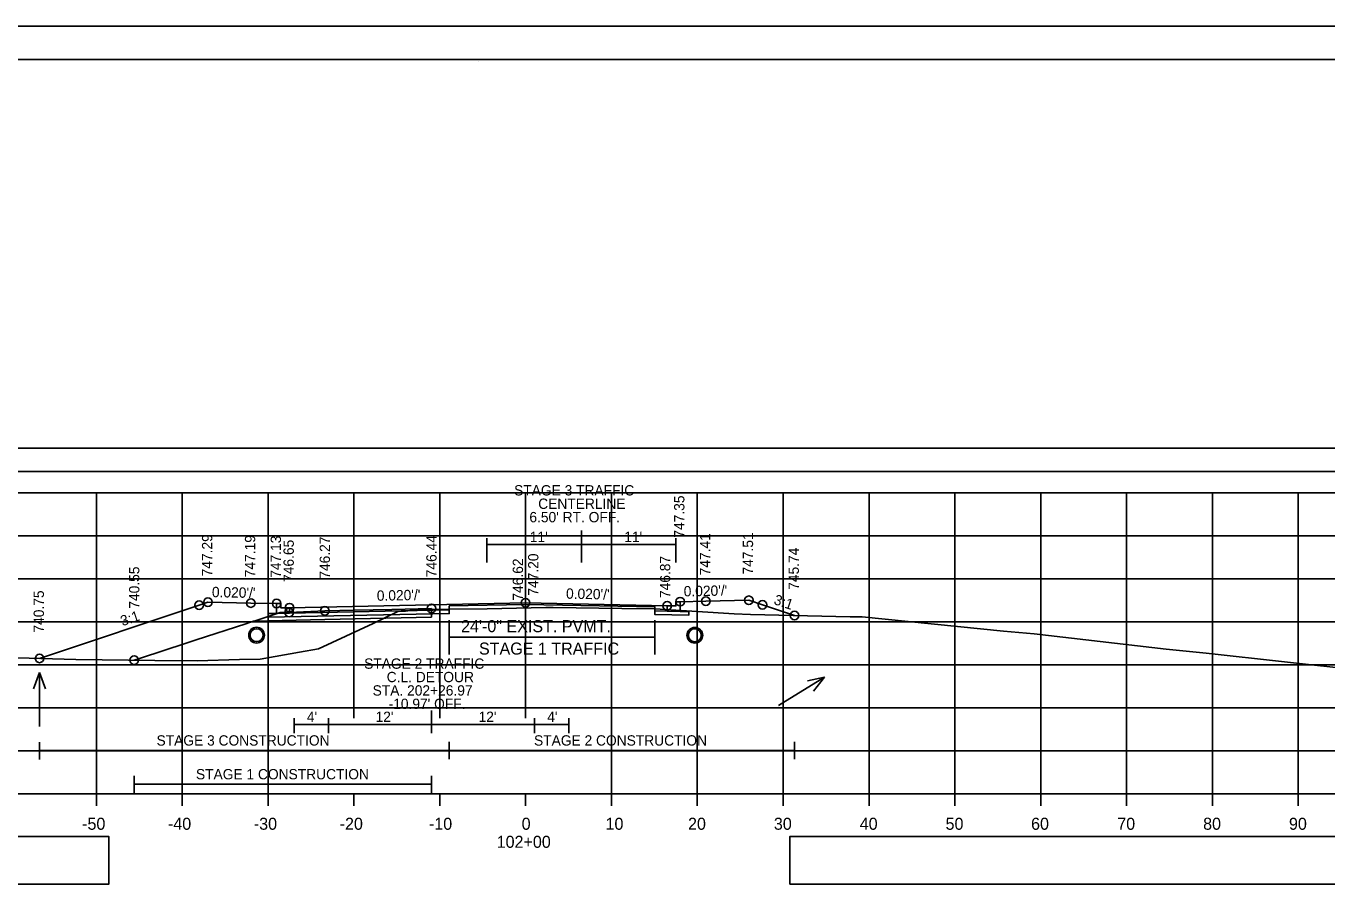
# Model space of a CAD drawing. Extents: x 1202951 to 1376887, y 378065 to 728038.
# Drawn here: x 1376526.5 to 1376677.9, y 378520.8 to 378621.2 of the extents above; entities that cross this region are included whole.
import ezdxf

# ---------------------------------------------------------------- set-up
doc = ezdxf.new("R2010")
doc.units = 0
for name, color, linetype in [('Default', 7, 'Continuous'), ('R_Alt Surface', 7, 'Continuous'), ('R_Axis', 7, 'Continuous'), ('R_Axis Annot', 7, 'Continuous'), ('R_Border', 7, 'Continuous'), ('R_Detour', 7, 'Continuous'), ('R_Detour Annot', 7, 'Continuous'), ('R_Dimension', 7, 'Continuous'), ('R_Exist Surface', 7, 'Continuous'), ('R_Fin Surface', 7, 'Continuous'), ('R_Grid', 7, 'Continuous'), ('R_MOT', 7, 'Continuous'), ('R_No Plot', 7, 'Continuous'), ('R_Proposed Const Limits', 7, 'Continuous'), ('R_Water', 7, 'Continuous'), ('R_Water Annot', 7, 'Continuous'), ('R_Xsect Elev', 7, 'Continuous'), ('R_Xsect Slope', 7, 'Continuous')]:
    doc.layers.add(name, color=color, linetype=linetype)

msp = doc.modelspace()

# ---------------------------------------------------------------- linework, layer by layer
at = {"layer": 'Default'}
for points in [[(1376555.67, 378553.95), (1376556.16, 378553.95), (1376556.17, 378553.45), (1376557.17, 378553.47), (1376557.17, 378552.84), (1376555.67, 378552.81)], [(1376602.67, 378554.17), (1376602.18, 378554.17), (1376602.17, 378553.67), (1376601.17, 378553.69), (1376601.17, 378553.06), (1376602.67, 378553.03)]]:
    msp.add_lwpolyline(points, close=True, dxfattribs=at)
at = {"layer": 'R_Alt Surface'}
for points in [[(1376434.67, 378569.32), (1376710.2, 378569.32), (1376710.2, 378572.02), (1376434.67, 378572.02)], [(1376557.17, 378552.84), (1376555.67, 378552.81), (1376554.67, 378552.79), (1376554.67, 378552.37), (1376575.77, 378552.79), (1376575.77, 378553.21)], [(1376557.17, 378553.47), (1376557.17, 378552.84), (1376575.77, 378553.21), (1376575.77, 378553.67), (1376584.67, 378553.85), (1376599.73, 378553.55), (1376599.73, 378553.09), (1376601.17, 378553.06), (1376601.17, 378553.69), (1376601.17, 378553.69), (1376584.67, 378554.02), (1376557.17, 378553.47)], [(1376603.67, 378553.01), (1376602.67, 378553.03), (1376601.17, 378553.06), (1376599.73, 378553.09), (1376599.73, 378552.67), (1376603.67, 378552.59)], [(1376434.67, 378521.29), (1376536.14, 378521.29), (1376536.14, 378526.82), (1376434.67, 378526.82)], [(1376615.43, 378521.29), (1376726.14, 378521.29), (1376726.14, 378526.82), (1376615.43, 378526.82)]]:
    msp.add_lwpolyline(points, close=True, dxfattribs=at)
msp.add_lwpolyline([(1376555.67, 378553.95), (1376555.67, 378552.81), (1376557.17, 378552.84), (1376575.77, 378553.21), (1376575.77, 378553.67), (1376584.67, 378553.85), (1376599.73, 378553.55), (1376599.73, 378553.09), (1376601.17, 378553.06), (1376602.67, 378553.03), (1376602.67, 378554.17)], dxfattribs=at)
at = {"layer": 'R_Axis'}
for p, q in [((1376434.67, 378531.82), (1376734.67, 378531.82)), ((1376534.67, 378530.42), (1376534.67, 378531.82)), ((1376544.67, 378530.42), (1376544.67, 378531.82)), ((1376554.67, 378530.42), (1376554.67, 378531.82)), ((1376564.67, 378530.42), (1376564.67, 378531.82)), ((1376574.67, 378530.42), (1376574.67, 378531.82)), ((1376584.67, 378530.42), (1376584.67, 378531.82)), ((1376594.67, 378530.42), (1376594.67, 378531.82)), ((1376604.67, 378530.42), (1376604.67, 378531.82)), ((1376614.67, 378530.42), (1376614.67, 378531.82)), ((1376624.67, 378530.42), (1376624.67, 378531.82)), ((1376634.67, 378530.42), (1376634.67, 378531.82)), ((1376644.67, 378530.42), (1376644.67, 378531.82)), ((1376654.67, 378530.42), (1376654.67, 378531.82)), ((1376664.67, 378530.42), (1376664.67, 378531.82)), ((1376674.67, 378530.42), (1376674.67, 378531.82))]:
    msp.add_line(p, q, dxfattribs=at)
at = {"layer": 'R_Border'}
for p, q in [((1376426.67, 378617.28), (1376742.85, 378617.28)), ((1376579.19, 378617.02), (1376579.19, 378617.02)), ((1376579.19, 378617.02), (1376579.19, 378617.02))]:
    msp.add_line(p, q, dxfattribs=at)
at = {"layer": 'R_Detour'}
for p, q in [((1376573.7, 378541.52), (1376573.7, 378538.86)), ((1376557.7, 378540.61), (1376557.7, 378538.86)), ((1376557.7, 378539.86), (1376561.7, 378539.86)), ((1376561.7, 378540.61), (1376561.7, 378538.86)), ((1376561.7, 378539.86), (1376573.7, 378539.86)), ((1376573.7, 378540.61), (1376573.7, 378538.86)), ((1376573.7, 378539.86), (1376585.7, 378539.86)), ((1376585.7, 378540.61), (1376585.7, 378538.86)), ((1376585.7, 378539.86), (1376589.7, 378539.86)), ((1376589.7, 378540.61), (1376589.7, 378538.86))]:
    msp.add_line(p, q, dxfattribs=at)
for points in [[(1376539.08, 378547.37), (1376539.8, 378547.6), (1376540.39, 378547.79), (1376541.11, 378548.03), (1376541.24, 378548.07), (1376546.3, 378549.71), (1376552.08, 378551.59), (1376552.5, 378551.73), (1376552.98, 378551.89), (1376553.29, 378551.99), (1376556.09, 378552.9), (1376556.74, 378552.91), (1376557.13, 378552.91), (1376559.64, 378553.02), (1376561.28, 378553.09), (1376564.74, 378553.17), (1376569.1, 378553.27), (1376573.7, 378553.38)], [(1376561.28, 378552.09), (1376573.7, 378552.38), (1376573.7, 378553.38)], [(1376561.28, 378552.09), (1376552.98, 378551.89)]]:
    msp.add_lwpolyline(points, dxfattribs=at)
at = {"layer": 'R_Dimension'}
for points in [[(1376528.06, 378537.81), (1376528.06, 378535.81)], [(1376528.06, 378536.84), (1376575.77, 378536.84)], [(1376575.77, 378537.84), (1376575.77, 378535.84)], [(1376575.77, 378536.84), (1376616, 378536.84)], [(1376616, 378537.84), (1376616, 378535.84)], [(1376539.08, 378533.91), (1376539.08, 378531.91)], [(1376573.7, 378533.91), (1376573.7, 378531.91)], [(1376539.08, 378532.91), (1376573.7, 378532.91)]]:
    msp.add_lwpolyline(points, dxfattribs=at)
at = {"layer": 'R_Exist Surface'}
msp.add_lwpolyline([(1376524.12, 378547.69), (1376532.29, 378547.44), (1376541.47, 378547.34), (1376546.41, 378547.28), (1376551.36, 378547.45), (1376553.76, 378547.48), (1376558.34, 378548.31), (1376560.55, 378548.68), (1376566.93, 378551.63), (1376569.78, 378553.01), (1376570.67, 378553.08), (1376571.96, 378553.25), (1376574.05, 378553.26), (1376575.77, 378553.3), (1376580.19, 378553.35), (1376587.02, 378553.48), (1376587.88, 378553.49), (1376595.86, 378553.39), (1376599.73, 378553.32), (1376608.98, 378552.77), (1376610.87, 378552.66), (1376622.49, 378552.41), (1376623.88, 378552.42), (1376640.34, 378550.72), (1376643.91, 378550.41), (1376659.29, 378548.66), (1376663.94, 378548.16), (1376682.2, 378546.14)], dxfattribs=at)
for centre in [(1376553.33, 378550.27), (1376604.38, 378550.26)]:
    msp.add_circle(centre, 0.917, dxfattribs=at)
at = {"layer": 'R_Fin Surface'}
for p, q in [((1376575.77, 378552.03), (1376575.77, 378548.03)), ((1376599.73, 378552.03), (1376599.73, 378548.03)), ((1376575.77, 378550.03), (1376599.73, 378550.03))]:
    msp.add_line(p, q, dxfattribs=at)
for points in [[(1376528.06, 378547.57), (1376546.64, 378553.76), (1376547.67, 378554.11), (1376552.67, 378554.01), (1376555.67, 378553.95), (1376556.16, 378553.95), (1376556.17, 378553.45), (1376557.17, 378553.47), (1376584.67, 378554.02), (1376601.17, 378553.69), (1376602.17, 378553.67), (1376602.18, 378554.17), (1376602.67, 378554.17), (1376605.67, 378554.23), (1376610.67, 378554.33), (1376612.25, 378553.8), (1376616, 378552.55)], [(1376547.67, 378554.11), (1376552.67, 378554.01), (1376555.67, 378553.95), (1376556.16, 378553.95), (1376556.17, 378553.45), (1376557.17, 378553.47), (1376557.17, 378553.47), (1376584.67, 378554.02), (1376601.17, 378553.69), (1376601.17, 378553.69), (1376602.17, 378553.67), (1376602.18, 378554.17), (1376602.67, 378554.17), (1376605.67, 378554.23), (1376610.67, 378554.33)]]:
    msp.add_lwpolyline(points, dxfattribs=at)
at = {"layer": 'R_Grid'}
for p, q in [((1376434.67, 378566.82), (1376734.67, 378566.82)), ((1376534.67, 378531.82), (1376534.67, 378566.82)), ((1376544.67, 378531.82), (1376544.67, 378566.82)), ((1376554.67, 378531.82), (1376554.67, 378566.82)), ((1376564.67, 378540.62), (1376564.67, 378566.82)), ((1376574.67, 378540.62), (1376574.67, 378566.82)), ((1376584.67, 378540.62), (1376584.67, 378566.82)), ((1376594.67, 378531.82), (1376594.67, 378566.82)), ((1376604.67, 378531.82), (1376604.67, 378566.82)), ((1376614.67, 378531.82), (1376614.67, 378566.82)), ((1376624.67, 378531.82), (1376624.67, 378566.82)), ((1376634.67, 378531.82), (1376634.67, 378566.82)), ((1376644.67, 378531.82), (1376644.67, 378566.82)), ((1376654.67, 378531.82), (1376654.67, 378566.82)), ((1376664.67, 378531.82), (1376664.67, 378566.82)), ((1376674.67, 378531.82), (1376674.67, 378566.82)), ((1376434.67, 378561.82), (1376734.67, 378561.82)), ((1376434.67, 378556.82), (1376734.67, 378556.82)), ((1376434.67, 378551.82), (1376734.67, 378551.82)), ((1376434.67, 378546.82), (1376734.67, 378546.82)), ((1376434.67, 378541.82), (1376734.67, 378541.82)), ((1376434.67, 378536.82), (1376734.67, 378536.82)), ((1376434.67, 378531.82), (1376734.67, 378531.82))]:
    msp.add_line(p, q, dxfattribs=at)
at = {"layer": 'R_MOT'}
for p, q in [((1376591.17, 378562.47), (1376591.17, 378558.72)), ((1376580.17, 378561.56), (1376580.17, 378558.72)), ((1376580.17, 378560.81), (1376591.17, 378560.81)), ((1376591.17, 378560.81), (1376602.17, 378560.81)), ((1376602.17, 378561.56), (1376602.17, 378558.72))]:
    msp.add_line(p, q, dxfattribs=at)
at = {"layer": 'R_No Plot'}
msp.add_line((1376414.27, 378621.17), (1376747.6, 378621.17), dxfattribs=at)
for points in [[(1376414.26, 378621.17), (1376747.6, 378621.17), (1376747.6, 378407.83), (1376414.26, 378407.83)], [(1376660.59, 378617.28), (1376680.21, 378617.28), (1376680.21, 378607.4), (1376696.32, 378607.4), (1376719.52, 378607.4), (1376719.64, 378579.24), (1376742.85, 378579.24), (1376742.85, 378411.82), (1376426.67, 378411.82), (1376426.67, 378617.28)]]:
    msp.add_lwpolyline(points, close=True, dxfattribs=at)
for centre in [(1376547.67, 378554.11), (1376547.67, 378554.11), (1376602.67, 378554.17), (1376602.67, 378554.17), (1376605.67, 378554.23), (1376605.67, 378554.23), (1376610.67, 378554.33), (1376610.67, 378554.33), (1376546.64, 378553.76), (1376552.67, 378554.01), (1376552.67, 378554.01), (1376555.67, 378553.95), (1376555.67, 378553.95), (1376557.13, 378552.91), (1376557.17, 378553.47), (1376557.17, 378553.47), (1376561.28, 378553.09), (1376573.7, 378553.38), (1376584.67, 378554.02), (1376584.67, 378554.02), (1376601.17, 378553.69), (1376601.17, 378553.69), (1376612.25, 378553.8), (1376616, 378552.55), (1376616, 378552.55), (1376528.06, 378547.57), (1376528.06, 378547.57), (1376539.08, 378547.37)]:
    msp.add_circle(centre, 0.5, dxfattribs=at)
at = {"layer": 'R_Proposed Const Limits'}
for points in [[(1376547.67, 378554.11), (1376546.64, 378553.76), (1376546.64, 378553.76), (1376528.06, 378547.57)], [(1376610.67, 378554.33), (1376612.25, 378553.8), (1376612.25, 378553.8), (1376616, 378552.55)]]:
    msp.add_lwpolyline(points, dxfattribs=at)
at = {"layer": 'R_Water'}
for centre in [(1376553.33, 378550.27), (1376604.38, 378550.26)]:
    msp.add_circle(centre, 0.75, dxfattribs=at)
at = {"layer": 'R_Water Annot'}
for p, q in [((1376528.03, 378545.93), (1376527.33, 378544.01)), ((1376528.03, 378539.65), (1376528.03, 378545.93)), ((1376528.03, 378545.93), (1376528.73, 378544.01)), ((1376614.13, 378542.09), (1376619.49, 378545.37)), ((1376619.49, 378545.37), (1376617.49, 378544.97)), ((1376619.49, 378545.37), (1376618.22, 378543.77))]:
    msp.add_line(p, q, dxfattribs=at)
at = {"layer": 'R_Xsect Elev'}
msp.add_line((1376584.67, 378553.44), (1376584.67, 378560.66), dxfattribs=at)

# ---------------------------------------------------------------- texts
at = {"layer": 'R_Axis Annot'}
for s, p in [('24\'-0" EXIST. PVMT.', (1376577.15, 378550.62)), ('STAGE 1 TRAFFIC', (1376579.24, 378548.01)), ('-50', (1376533.01, 378527.62)), ('-40', (1376543.01, 378527.62)), ('-30', (1376553.01, 378527.62)), ('-20', (1376563.01, 378527.62)), ('-10', (1376573.41, 378527.62)), ('0', (1376584.21, 378527.62)), ('10', (1376593.98, 378527.62)), ('20', (1376603.59, 378527.62)), ('30', (1376613.59, 378527.62)), ('40', (1376623.59, 378527.62)), ('50', (1376633.59, 378527.62)), ('60', (1376643.55, 378527.62)), ('70', (1376653.59, 378527.62)), ('80', (1376663.59, 378527.62)), ('90', (1376673.59, 378527.62)), ('102+00', (1376581.3, 378525.52))]:
    msp.add_text(s, height=1.4, dxfattribs=at).set_placement(p)
at = {"layer": 'R_Detour'}
for s, p in [('STAGE 2 TRAFFIC', (1376565.86, 378546.36)), ('C.L. DETOUR', (1376568.49, 378544.8)), ('STA. 202+26.97', (1376566.85, 378543.24)), ("-10.97' OFF.", (1376568.71, 378541.68)), ("4'", (1376559.19, 378540.17)), ("12'", (1376567.19, 378540.17)), ("12'", (1376579.19, 378540.17)), ("4'", (1376587.19, 378540.17))]:
    msp.add_text(s, height=1.2, dxfattribs=at).set_placement(p)
at = {"layer": 'R_Detour Annot'}
for s, p in [('746.27', (1376561.88, 378556.84)), ('746.44', (1376574.3, 378557.01)), ('740.55', (1376539.68, 378553.35))]:
    msp.add_text(s, height=1.2, rotation=90, dxfattribs=at).set_placement(p)
at = {"layer": 'R_Dimension'}
for s, p in [('STAGE 3 CONSTRUCTION', (1376541.68, 378537.42)), ('STAGE 2 CONSTRUCTION', (1376585.65, 378537.42)), ('STAGE 1 CONSTRUCTION', (1376546.27, 378533.49))]:
    msp.add_text(s, height=1.2, dxfattribs=at).set_placement(p)
at = {"layer": 'R_MOT'}
for s, p in [('STAGE 3 TRAFFIC ', (1376583.33, 378566.53)), ('CENTERLINE', (1376586.14, 378564.97)), ("6.50' RT. OFF.", (1376585.11, 378563.41)), ("11'", (1376585.16, 378561.12)), ("11'", (1376596.16, 378561.12))]:
    msp.add_text(s, height=1.2, dxfattribs=at).set_placement(p)
at = {"layer": 'R_Xsect Elev'}
for s, p in [('747.35', (1376603.17, 378561.62)), ('747.51', (1376611.17, 378557.33)), ('747.51', (1376611.17, 378557.33)), ('747.29', (1376548.17, 378557.11)), ('747.29', (1376548.17, 378557.11)), ('747.19', (1376553.17, 378557.01)), ('747.19', (1376553.17, 378557.01)), ('747.13', (1376556.17, 378556.95)), ('747.13', (1376556.17, 378556.95)), ('746.65', (1376557.67, 378556.47)), ('746.65', (1376557.67, 378556.47)), ('747.41', (1376606.17, 378557.23)), ('747.41', (1376606.17, 378557.23)), ('746.62', (1376584.37, 378554.29)), ('747.20', (1376586.16, 378554.87)), ('746.87', (1376601.52, 378554.59)), ('745.74', (1376616.5, 378555.55)), ('745.74', (1376616.5, 378555.55)), ('740.75', (1376528.56, 378550.57)), ('740.75', (1376528.56, 378550.57))]:
    msp.add_text(s, height=1.2, rotation=90, dxfattribs=at).set_placement(p)
at = {"layer": 'R_Xsect Slope'}
for s, rotation, p in [("0.020'/'", 1.1458, (1376603.1, 378554.78)), ("0.020'/'", 358.8542, (1376548.12, 378554.7)), ("0.020'/'", 1.1458, (1376567.35, 378554.27)), ("0.020'/'", 358.8542, (1376589.37, 378554.52)), ('3:1', 341.5651, (1376613.49, 378553.91)), ('3:1', 18.4349, (1376537.71, 378551.31))]:
    msp.add_text(s, height=1.2, rotation=rotation, dxfattribs=at).set_placement(p)

doc.saveas('drawing.dxf')
